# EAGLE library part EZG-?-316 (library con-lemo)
LEMO Connector Source: http://www.lemo.com/pdfs/catalog/ROW/German/unipole_multipole.pdf
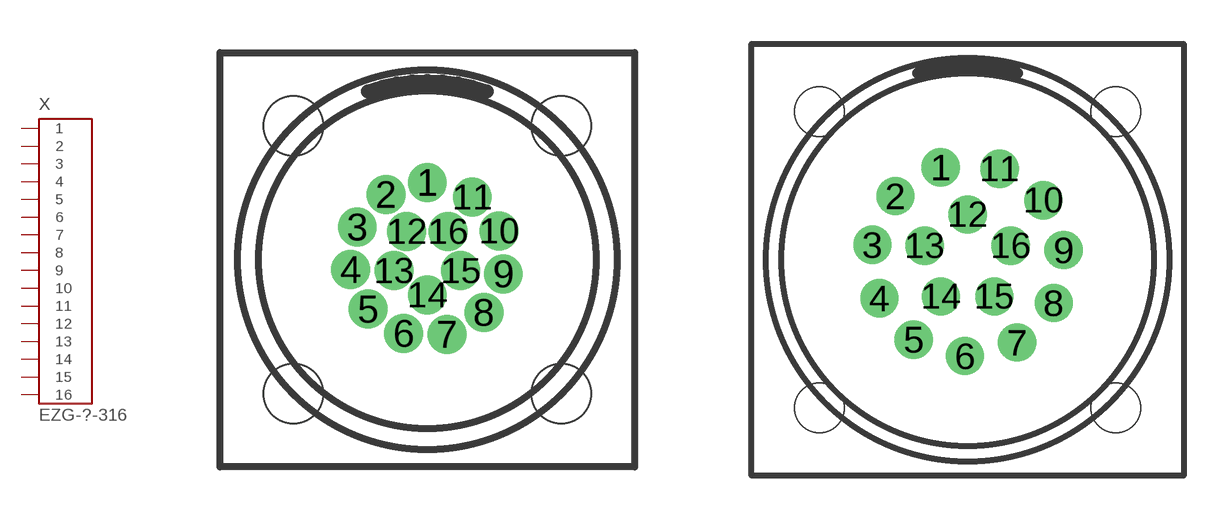
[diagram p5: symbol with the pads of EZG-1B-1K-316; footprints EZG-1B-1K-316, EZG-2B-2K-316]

Designator prefix X

## EZG-1B-316 (OC_FARNELL: unknown; OC_NEWARK: unknown)  [EZG-1B-1K-316]
1  1  pas
2  2  pas
3  3  pas
4  4  pas
5  5  pas
6  6  pas
7  7  pas
8  8  pas
9  9  pas
10  10  pas
11  11  pas
12  12  pas
13  13  pas
14  14  pas
15  15  pas
16  16  pas

## EZG-1K-316 (OC_FARNELL: unknown; OC_NEWARK: unknown)  [EZG-1B-1K-316]
Pads as for EZG-1B-1K-316

## EZG-2B-316 (OC_FARNELL: unknown; OC_NEWARK: unknown)  [EZG-2B-2K-316]
Pads as for EZG-1B-1K-316

## EZG-2K-316 (OC_FARNELL: unknown; OC_NEWARK: unknown)  [EZG-2B-2K-316]
Pads as for EZG-1B-1K-316

## Footprint EZG-1B-1K-316 (pad centres in mm)
LEMO Connector Source: http://www.lemo.com/pdfs/catalog/ROW/German/unipole_multipole.pdf
drill 0.6 pad 1 round: 1 0,2.2; 2 -1.18,1.857; 3 -1.992,0.934; 4 -2.182,-0.28; 5 -1.691,-1.407; 6 -0.672,-2.095; 7 0.556,-2.129; 8 1.611,-1.498; 9 2.163,-0.4; 10 2.04,0.823; 11 1.281,1.789; 12 -0.588,0.809; 13 -0.951,-0.309; 14 0,-1; 15 0.951,-0.309; 16 0.588,0.809
hole 1.7 at -3.81,3.81
hole 1.7 at 3.81,3.81
hole 1.7 at 3.81,-3.81
hole 1.7 at -3.81,-3.81

## Footprint EZG-2B-2K-316 (pad centres in mm)
LEMO Connector Source: http://www.lemo.com/pdfs/catalog/ROW/German/unipole_multipole.pdf
drill 0.8 pad 1.3 round: 1 -0.922,3.169; 2 -2.478,2.18; 3 -3.26,0.51; 4 -3.025,-1.318; 5 -1.846,-2.735; 6 -0.091,-3.299; 7 1.693,-2.833; 8 2.948,-1.483; 9 3.284,0.33; 10 2.594,2.04; 11 1.095,3.113; 12 0,1.55; 13 -1.474,0.479; 14 -0.911,-1.254; 15 0.911,-1.254; 16 1.474,0.479
hole 1.7 at -5.08,5.08
hole 1.7 at 5.08,5.08
hole 1.7 at 5.08,-5.08
hole 1.7 at -5.08,-5.08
